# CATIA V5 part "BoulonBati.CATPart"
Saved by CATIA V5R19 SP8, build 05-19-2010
Part number: BoulonBati
Bounding box of the stored display mesh (mm): x -38 to 34, y -8 to 8, z 742 to 758
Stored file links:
  G:\EU_thinkMotion\CFAO_2010\MMS_groupe3\MMS_groupe3\A reprendre\fovide\fovide\BoulonBati.CATPart
  C:\Users\Rodger\Desktop\Boulon.CATPart
  G:\EU_thinkMotion\CFAO_2010\MMS_groupe3\MMS_groupe3\A reprendre\fovide\fovide\fovide.CATProduct
  G:\EU_thinkMotion\CFAO_2010\MMS_groupe3\MMS_groupe3\A reprendre\fovide\fovide\Bati.CATPart
  C:\Users\Rodger\Desktop\Part11.CATPart
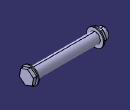
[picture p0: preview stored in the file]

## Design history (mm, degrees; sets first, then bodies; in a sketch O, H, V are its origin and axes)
Parameters
  Diametre = 10 mm
  Longueur = 60 mm
Set1
  DatumSurface1: linked copy from another document
  Point1: linked copy from another document
Body1 (main body)
Body2
  Sketch1 on DatumSurface1, origin (30, 0, 30), H (0, 0, -1), V (0, 1, 0)
    circle A1 centre (-720, 0) radius 8
    point P1 (-720, 0)
    reference projected point E1 (-720, 0) from Point1
    radius A1 = 8 {= Diametre *8/10}
    coincidence: P1 E1
  Pad1: profile Sketch1, direction (1, 0, 0), length 1
  Sketch2 on end face of Pad1, origin (31, 0, 32), H (0, 0, -1), V (0, 1, 0)
    point P1 (-718, 0)
    point P2 (-715.5061, -6.5407)
    point P3 (-711.0887, -1.1106)
    point P4 (-713.5825, 5.4301)
    point P5 (-720.4939, 6.5407)
    point P6 (-724.9113, 1.1106)
    point P7 (-722.4175, -5.4301)
    point P8 (-713.2974, -3.8256)
    line L1 (-715.5061, -6.5407) -> (-711.0887, -1.1106)
    line L2 (-711.0887, -1.1106) -> (-713.5825, 5.4301)
    line L3 (-713.5825, 5.4301) -> (-720.4939, 6.5407)
    line L4 (-720.4939, 6.5407) -> (-724.9113, 1.1106)
    line L5 (-724.9113, 1.1106) -> (-722.4175, -5.4301)
    line L6 (-722.4175, -5.4301) -> (-715.5061, -6.5407)
    construction line L7 (-718, 0) -> (-713.2974, -3.8256)
    construction circle A1 centre (-718, 0) radius 7
    construction arc A2 centre (-724.9113, 1.1106) radius 7 from (-720.4939, 6.5407) to (-722.4175, -5.4301) cw
    construction arc A3 centre (-711.0887, -1.1106) radius 7 from (-713.5825, 5.4301) to (-715.5061, -6.5407) ccw
    reference projected point E1 (-718, 0) from Point1
    radius A1 = 7 {= Diametre *7/10}
    coincidence: A1 P2, A1 P3, A1 P4, A1 P5, A1 P6, A1 P7, A2 P1, A3 P1, P1 E1
    midpoint: P8 L1
    parallelism: L1 L4
  Pad2: profile Sketch2, direction (1, 0, 0), length 3
  Sketch3 on start face of Pad1, origin (30, 0, 30), H (0, 0, -1), V (0, -1, 0)
    circle A1 centre (-720, 0) radius 5
    point P1 (-720, 0)
    reference projected point E1 (-720, 0) from Point1
    radius A1 = 5 {= Diametre /2}
    coincidence: P1 E1
  Pad3: profile Sketch3, direction (-1, 0, 0), length 60 {= Longueur}
  Sketch4 on end face of Pad3, origin (-30, 0, -50), H (0, 0, -1), V (0, -1, 0)
    circle A1 centre (-800, 0) radius 8
    point P1 (-800, 0)
    reference projected point E1 (-800, 0) from Point1
    radius A1 = 8 {= Diametre *8/10}
    coincidence: P1 E1
  Pad4: profile Sketch4, direction (-1, 0, 0), length 1
  Sketch5 on end face of Pad4, origin (-31, 0, -52), H (0, 0, -1), V (0, -1, 0)
    point P1 (-802, 0)
    point P2 (-802.0478, -6.9998)
    point P3 (-795.9619, -3.5413)
    point P4 (-795.9141, 3.4585)
    point P5 (-801.9522, 6.9998)
    point P6 (-808.0381, 3.5413)
    point P7 (-808.0859, -3.4585)
    point P8 (-799.0048, -5.2706)
    line L1 (-802.0478, -6.9998) -> (-795.9619, -3.5413)
    line L2 (-795.9619, -3.5413) -> (-795.9141, 3.4585)
    line L3 (-795.9141, 3.4585) -> (-801.9522, 6.9998)
    line L4 (-801.9522, 6.9998) -> (-808.0381, 3.5413)
    line L5 (-808.0381, 3.5413) -> (-808.0859, -3.4585)
    line L6 (-808.0859, -3.4585) -> (-802.0478, -6.9998)
    construction line L7 (-802, 0) -> (-799.0048, -5.2706)
    construction circle A1 centre (-802, 0) radius 7
    construction arc A2 centre (-808.0381, 3.5413) radius 7 from (-801.9522, 6.9998) to (-808.0859, -3.4585) cw
    construction arc A3 centre (-795.9619, -3.5413) radius 7 from (-795.9141, 3.4585) to (-802.0478, -6.9998) ccw
    reference projected point E1 (-802, 0) from Point1
    radius A1 = 7 {= Diametre *7/10}
    coincidence: A1 P2, A1 P3, A1 P4, A1 P5, A1 P6, A1 P7, A2 P1, A3 P1, P1 E1
    midpoint: P8 L1
    parallelism: L1 L4
  Pad5: profile Sketch5, direction (-1, 0, 0), length 3
  Sketch6 on end face of Pad5, origin (-34, 0, -58), H (0, 0, -1), V (0, -1, 0)
    circle A1 centre (-808, 0) radius 5
    point P1 (-808, 0)
    reference projected point E1 (-808, 0) from Point1
    radius A1 = 5 {= Diametre /2}
    coincidence: P1 E1
  Pad6: profile Sketch6, direction (-1, 0, 0), length 4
